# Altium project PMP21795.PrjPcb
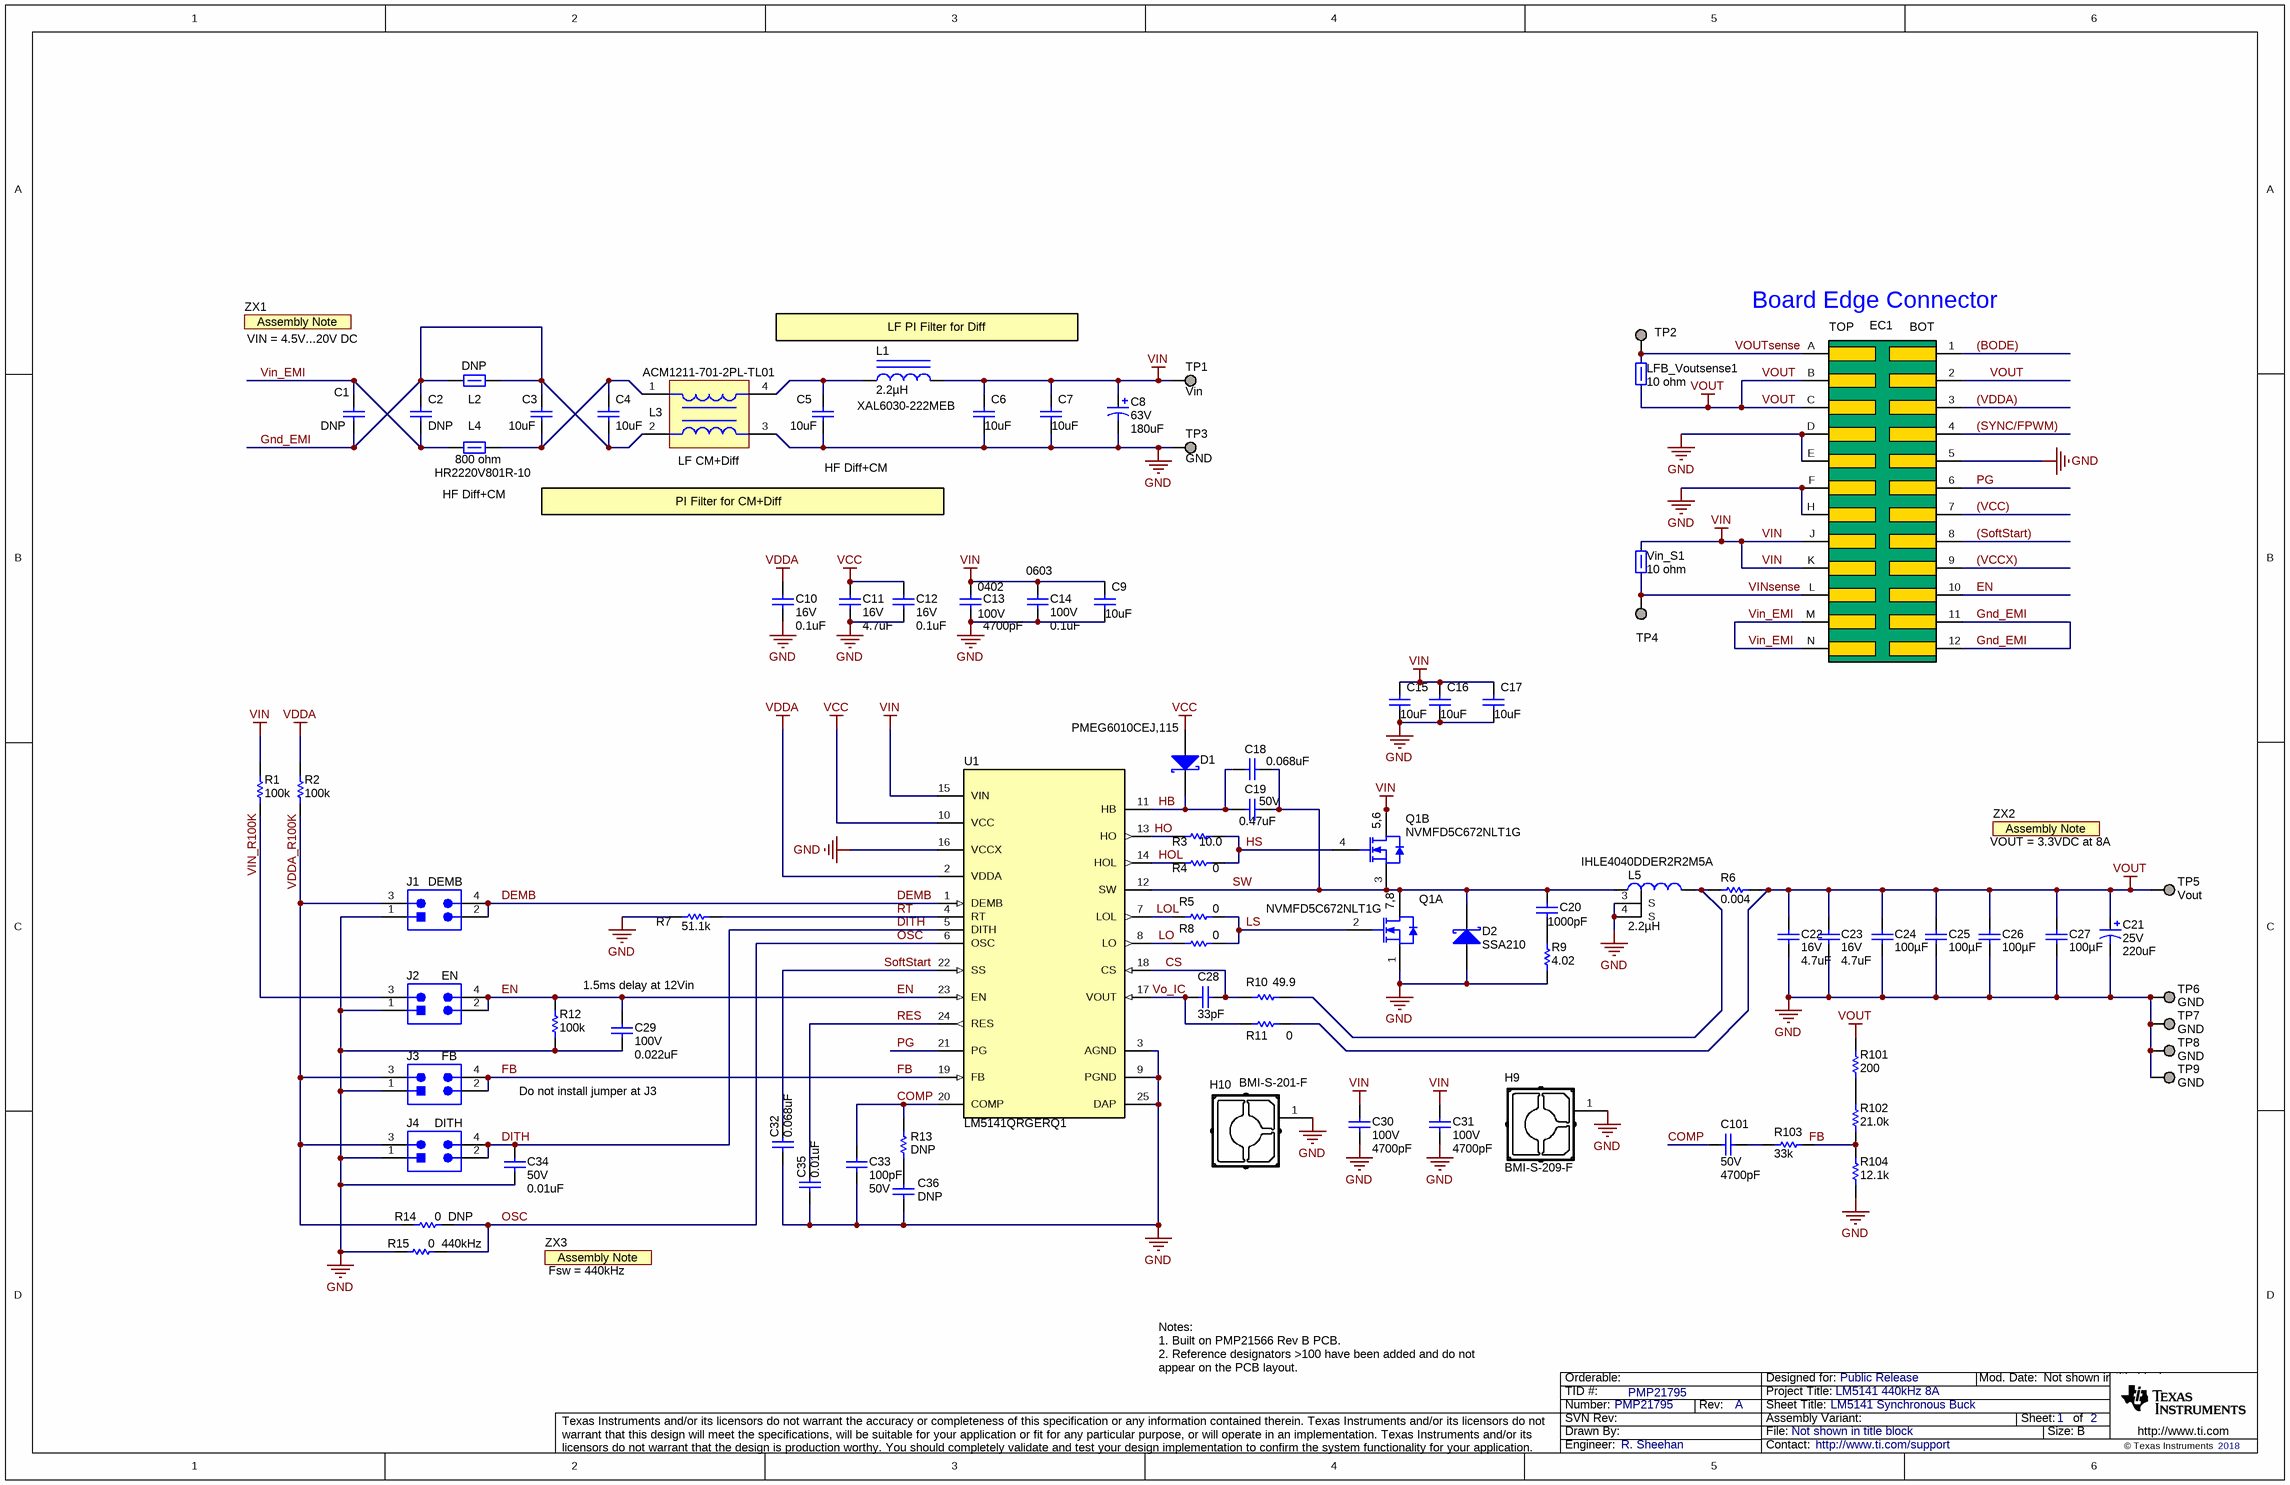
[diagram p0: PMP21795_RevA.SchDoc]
TID: PMP21795; TechSupport: http://www.ti.com/support; SCH_Rev: A; PRJ_Title: LM5141 440kHz 8A; PRJ_Number: PMP21795; PRJ_Engineer: R. Sheehan; PRJ_Customer: Public Release; PCB_Rev: B; PCB_Layout: Robert Loke; CopyrightYear: 2018
2 sheets, 104 parts. Net scope: global (net labels, ports and power ports of the same name join across sheets).
Board file: PMP21566_RevB_PCB.PcbDoc
Sheets:
  PMP21795_RevA.SchDoc
  PMP21795_RevA_HW.SchDoc

## Sheet PMP21795_RevA.SchDoc: LM5141 Synchronous Buck
size 431 x 279 mm; Date: Not shown in title block; ApprovedBy: Not shown in title block; CheckedBy: Not shown in title block; Author: Not shown in title block; CompanyName: Not shown in title block; Engineer: Not shown in title block; Organization: Not shown in title block; Address1: Not shown in title block; Address2: Not shown in title block; Address3: Not shown in title block; Address4: Not shown in title block; DocumentNumber: 1; Revision: Use project parameter SCH_Rev; SheetNumber: 1; SheetTotal: 2; PageSetup: Record=PageOptions¦CenterHorizontal=True¦CenterVertical=True¦PrintScale=0.96¦XCorrection=1.00¦YCorrection=1.00¦PrintKind=0¦BorderSize=5000000¦LeftOffset=0¦BottomOffset=0¦Orientation=2¦PaperLength=1000¦PaperWidth=1000¦Scale=100¦PaperSource=15¦PrintQuality=-3¦MediaType=1¦DitherType=10¦PrintScaleMode=1¦PaperKind=11x17¦PaperIndex=17

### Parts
C1  DNP  [1210_270L]
C2  DNP  [1210_270L]
C3  ValueDisplayed: 10uF  [1210_270L]  (hidden comment: GRM32ER71J106KA12L)
C4  ValueDisplayed: 10uF  [1210_270L]  (hidden comment: GRM32ER71J106KA12L)
C5  ValueDisplayed: 10uF  [1210_270L]  (hidden comment: GRM32ER71J106KA12L)
C6  ValueDisplayed: 10uF  [1210_270L]  (hidden comment: GRM32ER71J106KA12L)
C7  ValueDisplayed: 10uF  [1210_270L]  (hidden comment: GRM32ER71J106KA12L)
C8  VDC_V: 63V  ValueDisplayed: 180uF  [UCZ_1250x1350]  (hidden comment: UCZ1J181MNQ1MS)
C9  ValueDisplayed: 10uF  [1210_270L]  (hidden comment: GRM32ER71J106KA12L)
C10  VDC_V: 16V  ValueDisplayed: 0.1uF  [0402S]  (hidden comment: C0402C104K4RACAUTO)
C11  VDC_V: 16V  ValueDisplayed: 4.7uF  [0603S]  (hidden comment: GRM188Z71C475KE21D)
C12  VDC_V: 16V  ValueDisplayed: 0.1uF  [0402S]  (hidden comment: C0402C104K4RACAUTO)
C13  PackageReference: 0402  VDC_V: 100V  ValueDisplayed: 4700pF  [0402S]  (hidden comment: GRM155R72A472KA01D)
C14  Cap_Case: 0603  VDC_V: 100V  ValueDisplayed: 0.1uF  [0603S]  (hidden comment: GCJ188R72A104KA01D)
C15  ValueDisplayed: 10uF  [1210_270L]  (hidden comment: GRM32ER71J106KA12L)
C16  ValueDisplayed: 10uF  [1210_270L]  (hidden comment: GRM32ER71J106KA12L)
C17  ValueDisplayed: 10uF  [1210_270L]  (hidden comment: GRM32ER71J106KA12L)
C18  ValueDisplayed: 0.068uF  [0402S]  (hidden comment: C1005X7R1H683K050BB)
C19  VDC_V: 50V  ValueDisplayed: 0.47uF  [0603S]  (hidden comment: CGA3E3X7R1H474K080AB)
C20  ValueDisplayed: 1000pF  [0603S]  (hidden comment: 06031C102JAT2A)
C21  VDC_V: 25V  ValueDisplayed: 220uF  [SM_RADIAL_F]  (hidden comment: EEE-FK1E221P)
C22  VDC_V: 16V  ValueDisplayed: 4.7uF  [0603S]  (hidden comment: GRM188Z71C475KE21D)
C23  VDC_V: 16V  ValueDisplayed: 4.7uF  [0603S]  (hidden comment: GRM188Z71C475KE21D)
C24  ValueDisplayed: 100µF  [1210_280]  (hidden comment: LMK325ABJ107MMHT)
C25  ValueDisplayed: 100µF  [1210_280]  (hidden comment: LMK325ABJ107MMHT)
C26  ValueDisplayed: 100µF  [1210_280]  (hidden comment: LMK325ABJ107MMHT)
C27  ValueDisplayed: 100µF  [1210_280]  (hidden comment: LMK325ABJ107MMHT)
C28  ValueDisplayed: 33pF  [0201L]  (hidden comment: GRM0335C1H330JA01D)
C29  1.5ms delay at 12Vin  VDC_V: 100V  ValueDisplayed: 0.022uF  [0603M]
C30  VDC_V: 100V  ValueDisplayed: 4700pF  [0402S]  (hidden comment: GRM155R72A472KA01D)
C31  VDC_V: 100V  ValueDisplayed: 4700pF  [0402S]  (hidden comment: GRM155R72A472KA01D)
C32  ValueDisplayed: 0.068uF  [0402S]  (hidden comment: C1005X7R1H683K050BB)
C33  ValueDisplayed: 100pF  VDC_V: 50V  [0402]  (hidden comment: GRM1555C1H101JA01D)
C34  VDC_V: 50V  ValueDisplayed: 0.01uF  [0402S]  (hidden comment: C0402C103J5RACTU)
C35  ValueDisplayed: 0.01uF  [0402S]  (hidden comment: CGA2B3X7R1H103K050BB)
C36  DNP  [0402S]
C101  VDC_V: 50V  ValueDisplayed: 4700pF  [0402]  (hidden comment: GCM155R71H472KA37D)
D1  PMEG6010CEJ,115  [SOD-323F]
D2  SSA210  [SMA]
EC1  305-024-521-201  [Edge_Connector_EDAC_12x2]  (value not drawn)  (no BOM)
H9  BMI-S-209-F  [Laird_BMI-S-209-F]
H10  BMI-S-201-F  [Laird_BMI-S-201-F]
J1  DEMB  [TSW-102-07-G-D]
J2  EN  [TSW-102-07-G-D]
J3  FB  [TSW-102-07-G-D]
J4  DITH  [TSW-102-07-G-D]
L1  ValueDisplayed: 2.2µH  [XAL6030]  (hidden comment: XAL6030-222MEB)
L2  DNP  [2220_390]
L3  ACM1211-701-2PL-TL01  [TDK_ACM1211]
L4  800 ohm  PartNumber: HR2220V801R-10  [2220_390]
L5  ValueDisplayed: 2.2µH  [IHLE4040DD]  (hidden comment: IHLE4040DDER2R2M5A)
LFB_Voutsense1  value 10 ohm  [0402S]  (hidden comment: BLM15AX100SN1D)
Q1  NVMFD5C672NLT1G  [SO8FL_Dual]  (parts A,B of 2)
R1  ValueDisplayed: 100k  [0402S]  (hidden comment: CRCW0402100KFKED)
R2  ValueDisplayed: 100k  [0402S]  (hidden comment: CRCW0402100KFKED)
R3  ValueDisplayed: 10.0  [0402S]  (hidden comment: RMCF0402JT10R0)
R4  ValueDisplayed: 0  [0402S]  (hidden comment: RK73Z1ETTP)
R5  ValueDisplayed: 0  [0402S]  (hidden comment: RK73Z1ETTP)
R6  ValueDisplayed: 0.004  [2512_WIDE]  (hidden comment: KRL6432E-M-R004-F-T1)
R7  ValueDisplayed: 51.1k  [0402S]  (hidden comment: CRCW040251K1FKED)
R8  ValueDisplayed: 0  [0402S]  (hidden comment: RK73Z1ETTP)
R9  ValueDisplayed: 4.02  [0603]  (hidden comment: CRCW06034R02FKEA)
R10  ValueDisplayed: 49.9  [0402S]  (hidden comment: RMCF0402FT49R9)
R11  ValueDisplayed: 0  [0402S]  (hidden comment: RK73Z1ETTP)
R12  ValueDisplayed: 100k  [0402S]  (hidden comment: CRCW0402100KFKED)
R13  DNP  [0402S]
R14  DNP  ValueDisplayed: 0  [0402S]
R15  440kHz  ValueDisplayed: 0  [0402S]
R101  ValueDisplayed: 200  [0402]  (hidden comment: CRCW0402200RFKED)
R102  ValueDisplayed: 21.0k  [0402]  (hidden comment: CRCW040221K0FKED)
R103  ValueDisplayed: 33k  [0402]  (hidden comment: CRCW040233K0JNED)
R104  ValueDisplayed: 12.1k  [0402]  (hidden comment: CRCW040212K1FKED)
TP1  Vin  [Keystone1598-2]
TP2  S1751-46  [Harwin_S1751-46]  (value not drawn)
TP3  GND  [Keystone1598-2]
TP4  S1751-46  [Harwin_S1751-46]  (value not drawn)
TP5  Vout  [Keystone1598-2]
TP6  GND  [Keystone1598-2]
TP7  GND  [Keystone1598-2]
TP8  GND  [Keystone1598-2]
TP9  GND  [Keystone1598-2]
U1  LM5141QRGERQ1  [RGE0024J]
Vin_S1  value 10 ohm  [0402S]  (hidden comment: BLM15AX100SN1D)
ZX1  VIN = 4.5V...20V DC  [AssemblyNote]  (no BOM)
ZX2  VOUT = 3.3VDC at 8A  [AssemblyNote]  (no BOM)
ZX3  Fsw = 440kHz  [AssemblyNote]  (no BOM)

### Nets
GND: C5.2 C6.2 C7.2 C8.2(-) C9.2 C10.1 C11.2 C12.1 C13.2 C14.2 C15.2 C16.2 C17.2 C21.2(-) C22.2 C23.2 C24.2 C25.2 C26.2 C27.2 C29.2 C30.2 C31.2 C32.2 C33.2 C34.1 C35.2 C36.2 D2.2(A) EC1.5 EC1.D EC1.E EC1.F EC1.H H9.1 H10.1 J1.1 J2.1 J3.1 J4.1 L3.3 L5.3(S) L5.4(S) Q1.1(S) R7.2 R9.1 R12.1 R15.2 R104.1 TP3.1 TP6.1 TP7.1 TP8.1 TP9.1 U1.3(AGND) U1.9(PGND) U1.16(VCCX) U1.25(DAP)
VCC: C11.1 C12.2 D1.2(A) U1.10(VCC)
VDDA: C10.2 R2.2 U1.2(VDDA)
VIN: C6.1 C7.1 C8.1(+) C9.1 C13.1 C14.1 C15.1 C16.1 C17.1 C30.1 C31.1 EC1.J EC1.K L1.2 Q1.5(D) Q1.6(D) R1.2 TP1.1 U1.15(VIN) Vin_S1.2
VOUT: C21.1(+) C22.1 C23.1 C24.1 C25.1 C26.1 C27.1 EC1.2 EC1.B EC1.C LFB_Voutsense1.1 R6.2 R11.1 R101.2 TP5.1
(BODE): EC1.1
(SoftStart): EC1.8
(SYNC/FPWM): EC1.4
(VCC): EC1.7
(VCCX): EC1.9
(VDDA): EC1.3
COMP: C33.1 C101.1 R13.2 U1.20(COMP)
CS: C28.1 R10.2 U1.18(CS)
DEMB: J1.2 J1.4 U1.1(DEMB)
DITH: C34.2 J4.2 J4.4 U1.5(DITH)
EN: C29.1 EC1.10 J2.2 J2.4 R12.2 U1.23(EN)
FB: J3.2 J3.4 U1.19(FB)
Gnd_EMI: C1.2 C2.1 C3.1 C4.2 EC1.11 EC1.12 L2.1 L2.2 L3.2
HB: C18.1 C19.2 D1.1(K) U1.11(HB)
HO: R3.1 U1.13(HO)
HOL: R4.1 U1.14(HOL)
HS: Q1.4(G) R3.2 R4.2
LO: R8.1 U1.8(LO)
LOL: R5.1 U1.7(LOL)
LS: Q1.2(G) R5.2 R8.2
OSC: R14.1 R15.1 U1.6(OSC)
PG: EC1.6 U1.21(PG)
RES: C35.1 U1.24(RES)
RT: R7.1 U1.4(RT)
SoftStart: C32.1 U1.22(SS)
SW: C18.2 C19.1 C20.1 D2.1(K) L5.1 Q1.3(S) Q1.7(D) Q1.8(D) U1.12(SW)
VDDA_R100K: J1.3 J3.3 J4.3 R2.1 R14.2
Vin_EMI: C1.1 C2.2 EC1.M EC1.N L4.1
VIN_R100K: J2.3 R1.1
VINsense: EC1.L TP4.1 Vin_S1.1
Vo_IC: C28.2 R11.2 U1.17(VOUT)
VOUTsense: EC1.A LFB_Voutsense1.2 TP2.1
NetC3_2: C3.2 C4.1 L3.1 L4.2
NetC5_1: C5.1 L1.1 L3.4
NetC20_2: C20.2 R9.2
NetC36_1: C36.1 R13.1
NetC101_2: C101.2 R103.2
NetL5_2: L5.2 R6.1 R10.1
NetR101_1: R101.1 R102.2
NetR102_1: R102.1 R103.1 R104.2

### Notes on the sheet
- (near EC1) Board Edge Connector
- LF PI Filter for Diff
- (near L4) HF Diff+CM
- (near L3) LF CM+Diff
- PI Filter for CM+Diff
- (near C5) HF Diff+CM
- Do not install jumper at J3
- Notes:
  1. Built on PMP21566 Rev B PCB.
  2. Reference designators >100 have been added and do not appear on the PCB layout.
- Labels drawn without touching a wire or pin: FB

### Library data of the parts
C1 C2 = CMP-0009229-2: CAP, CERM, 10 uF, 63 V, +/- 10%, X7R, 1210; Manufacturer: MuRata; PartNumber: GRM32ER71J106KA12L; TaMin_C: -55°C; Polarized: N; SizeAreaWB_mm2: 14.7; Value1: Unknown; U/M: EA; Value: 10uF; TaMax_C: 125°C; SizeZ_mm: 2.7; SizeX_mm: 3.2; SizeY_mm: 2.5; Cap_Case: 1210; Value2: 63V; SizeArea_mm2: 8; CompType: Capacitor; Cap_F: 10µF; AEC Category: Q200
C3-C7 C9 C15-C17 = CMP-0009229-2: CAP, CERM, 10 uF, 63 V, +/- 10%, X7R, 1210; Manufacturer: MuRata; TaMin_C: -55°C; Polarized: N; SizeAreaWB_mm2: 14.7; Value1: Unknown; U/M: EA; Value: 10uF; TaMax_C: 125°C; SizeZ_mm: 2.7; SizeX_mm: 3.2; SizeY_mm: 2.5; Cap_Case: 1210; Value2: 63V; SizeArea_mm2: 8; CompType: Capacitor; Cap_F: 10µF; AEC Category: Q200
C8 = CMP-0011410-2: CAP, AL, 180 uF, 63 V, +/- 20%, 0.2 ohm, AEC-Q200 Grade 1, SMD; Manufacturer: Nichicon; TaMin_C: -40°C; Polarized: Y; SizeAreaWB_mm2: 258.96; Value1: 0.2 ohm; U/M: EA; Value: 180uF; TaMax_C: 125°C; SizeZ_mm: 14.5; SizeX_mm: 14.6; SizeY_mm: 13.6; Cap_Case: 12.5x13.5mm; SizeArea_mm2: 198.56; CompType: Capacitor; Cap_F: 180µF; IRMS_A: 1A; AEC Category: Q200; AEC Grade: 1; ESR_ohm: 2d
C10 C12 = CMP-0006237-2: CAP, CERM, 0.1 uF, 16 V, +/- 10%, X7R, AEC-Q200 Grade 1, 0402; Manufacturer: Kemet; TaMin_C: -55°C; Polarized: N; SizeAreaWB_mm2: 3; Value1: Unknown; U/M: EA; Value: 0.1uF; TaMax_C: 125°C; SizeZ_mm: 0.6; SizeX_mm: 1; SizeY_mm: 0.5; Cap_Case: 0402; CompType: Capacitor; AEC Qualified: Y; Cap_F: 100nF; AEC Category: Q200
C11 C22 C23 = CMP-0064936-4: CAP, CERM, 4.7 uF, 16 V,+/- 10%, X7R, 0603; Manufacturer: MuRata; TaMin_C: -55°C; Polarized: N; SizeAreaWB_mm2: 4.68; Value1: Unknown; U/M: EA; Value: 4.7uF; TaMax_C: 125°C; SizeZ_mm: 1; SizeX_mm: 1.6; SizeY_mm: 0.8; Cap_Case: 0603; SizeArea_mm2: 1.28; CompType: Capacitor; Cap_F: 4.7µF; AEC Category: Q200
C13 = CMP-0006712-2: CAP, CERM, 4700 pF, 100 V, +/- 10%, X7R, 0402; Manufacturer: MuRata; TaMin_C: -55°C; Polarized: N; SizeAreaWB_mm2: 3; Value1: Unknown; U/M: EA; Value: 4700pF; TaMax_C: 125°C; SizeZ_mm: 0.6; SizeX_mm: 1; SizeY_mm: 0.5; CompType: Capacitor; Cap_F: 4.7nF; AEC Category: Q200
C14 = CMP-0064935-4: CAP, CERM, 0.1 uF, 100 V,+/- 10%, X7R, AEC-Q200 Grade 1, 0603; Manufacturer: MuRata; TaMin_C: -55°C; Polarized: N; SizeAreaWB_mm2: 4.68; Value1: Unknown; U/M: EA; Value: 0.1uF; TaMax_C: 125°C; SizeZ_mm: 1; SizeX_mm: 1.6; SizeY_mm: 0.8; SizeArea_mm2: 1.28; CompType: Capacitor; AEC Qualified: Y; Cap_F: 100nF; AEC Category: Q200
C18 C32 = CMP-0006299-2: CAP, CERM, 0.068 uF, 50 V, +/- 10%, X7R, 0402; Manufacturer: TDK; TaMin_C: -55°C; ESR_ohm: 0.05606; Polarized: N; SizeAreaWB_mm2: 3; Value1: 0.05606 ohm; U/M: EA; TaMax_C: 125°C; SizeZ_mm: 0.6; SizeX_mm: 1; SizeY_mm: 0.5; Cap_Case: 0402; Value2: 50V; CompType: Capacitor; Cap_F: 68nF; IRMS_A: 6.84724dA; AEC Category: Q200
C19 = CMP-0007096-4: CAP, CERM, 0.47 uF, 50 V, +/- 10%, X7R, AEC-Q200 Grade 1, 0603; Manufacturer: TDK; TaMin_C: -55°C; ESR_ohm: 0.01064; Polarized: N; SizeAreaWB_mm2: 4.68; Value1: 0.01064 ohm; U/M: EA; Value: 0.47uF; TaMax_C: 125°C; SizeZ_mm: 1; SizeX_mm: 1.6; SizeY_mm: 0.8; Cap_Case: 0603; SizeArea_mm2: 1.28; CompType: Capacitor; AEC Qualified: Y; Cap_F: 470nF; IRMS_A: 1.59966A; AEC Category: Q200
C20 = CMP-0006723-4: CAP, CERM, 1000 pF, 100 V, +/- 5%, X7R, 0603; Manufacturer: AVX; TaMin_C: -55°C; ESR_ohm: 2.76d; Polarized: N; SizeAreaWB_mm2: 4.68; Value1: 0.276 ohm; U/M: EA; Value: 1000pF; TaMax_C: 125°C; SizeZ_mm: 1; SizeX_mm: 1.6; SizeY_mm: 0.8; Cap_Case: 0603; Value2: 100V; SizeArea_mm2: 1.28; CompType: Capacitor; Cap_F: 1nF; AEC Category: Q200
C21 = CMP-0010714-1: CAP, AL, 220 uF, 25 V, +/- 20%, 0.16 ohm, AEC-Q200 Grade 2, SMD; Manufacturer: Panasonic; TaMin_C: -55°C; ESR_ohm: 1.6d; Polarized: Y; SizeAreaWB_mm2: 123.6; U/M: EA; Value: 220uF; TaMax_C: 105°C; SizeZ_mm: 10.2; SizeX_mm: 10; SizeY_mm: 8.3; Cap_Case: F; SizeArea_mm2: 83; CompType: Capacitor; Cap_F: 220µF; IRMS_A: 6dA; AEC Grade: 2; AEC Category: Q200
C24 C25 = LMK325ABJ107MMHT: CAP, CERM, 100 µF, 10 V, +/- 20%, X5R, AEC-Q200 Grade 3, 1210; Manufacturer: Taiyo Yuden; Polarized: N; CompType: Capacitor; Value: 100uF; U/M: EA; Cap_F: 0.0001; Tolerance_%: 20; Value1: Unknown; VDC_V: 10; Value2: 10V; TaMin_C: -55; TaMax_C: 85; Cap_Case: 1210; SizeArea_mm2: 8; SizeAreaWB_mm2: 14.7; SizeX_mm: 3.2; SizeY_mm: 2.5; SizeZ_mm: 2.8; AEC Category: Q200; AEC Qualified: Y; AEC Grade: 3
C26 C27 = LMK325ABJ107MMHT: CAP, CERM, 100 µF, 10 V,+/- 20%, X5R, AEC-Q200 Grade 3, 1210; Manufacturer: Taiyo Yuden; Polarized: N; CompType: Capacitor; Value: 100uF; U/M: EA; Cap_F: 0.0001; Tolerance_%: 20; VDC_V: 10; Value2: 10V; TaMin_C: -55; TaMax_C: 85; Cap_Case: 1210; AEC Category: Q200; AEC Qualified: Y; AEC Grade: 3; SizeArea_mm2: 8; SizeAreaWB_mm2: 14.7; SizeX_mm: 3.2; SizeY_mm: 2.5; SizeZ_mm: 2.8
C28 = GRM0335C1H330JA01D: CAP, CERM, 33 pF, 50 V,+/- 5%, C0G/NP0, 0201; Manufacturer: MuRata; Polarized: N; CompType: Capacitor; Value: 33pF; U/M: EA; Cap_F: 0.000000000033; Tolerance_%: 5; VDC_V: 50; Value2: 50V; TaMin_C: -55; TaMax_C: 125; Cap_Case: 0201; SizeArea_mm2: 0.18; SizeAreaWB_mm2: 2.08; SizeX_mm: 0.6; SizeY_mm: 0.3; SizeZ_mm: 0.26; AEC Category: Q200
C29 = CMP-0007086-4: CAP, CERM, 0.022 uF, 100 V, +/- 10%, X7R, AEC-Q200 Grade 1, 0603; Manufacturer: TDK; PartNumber: CGA3E2X7R2A223K080AA; TaMin_C: -55°C; ESR_ohm: 0.083542; Polarized: N; SizeAreaWB_mm2: 4.68; Value1: 0.083542 ohm; U/M: EA; TaMax_C: 125°C; SizeZ_mm: 1; SizeX_mm: 1.6; SizeY_mm: 0.8; Cap_Case: 0603; SizeArea_mm2: 1.28; CompType: Capacitor; AEC Qualified: Y; Cap_F: 22nF; IRMS_A: 6.09312dA; AEC Category: Q200
C30 C31 = CMP-0006712-2: CAP, CERM, 4700 pF, 100 V, +/- 10%, X7R, 0402; Manufacturer: MuRata; TaMin_C: -55°C; Polarized: N; SizeAreaWB_mm2: 3; Value1: Unknown; U/M: EA; Value: 4700pF; TaMax_C: 125°C; SizeZ_mm: 0.6; SizeX_mm: 1; SizeY_mm: 0.5; Cap_Case: 0402; CompType: Capacitor; Cap_F: 4.7nF; AEC Category: Q200
C33 = CMP-0006410-2: CAP, CERM, 100 pF, 50 V, +/- 5%, C0G/NP0, 0402; Manufacturer: MuRata; Polarized: N; Value: 100pF; U/M: EA; Value1: Unknown; TaMin_C: -55°C; TaMax_C: 125°C; SizeArea_mm2: 0.5; SizeAreaWB_mm2: 3; SizeX_mm: 1; SizeZ_mm: 0.6; AEC Category: Q200
C34 = CMP-0006236-2: CAP, CERM, 0.01 uF, 50 V, +/- 5%, X7R, 0402; Manufacturer: Kemet; TaMin_C: -55°C; Polarized: N; SizeAreaWB_mm2: 3; Value1: Unknown; U/M: EA; Value: 0.01uF; TaMax_C: 125°C; SizeZ_mm: 0.6; SizeX_mm: 1; SizeY_mm: 0.5; Cap_Case: 0402; CompType: Capacitor; Cap_F: 10nF; AEC Category: Q200
C35 = CMP-0006324-2: CAP, CERM, 0.01 uF, 50 V, +/- 10%, X7R, AEC-Q200 Grade 1, 0402; Manufacturer: TDK; TaMin_C: -55°C; ESR_ohm: 3.33065d; Polarized: N; SizeAreaWB_mm2: 3; Value1: 0.333065 ohm; U/M: EA; Value: 0.01uF; TaMax_C: 125°C; SizeZ_mm: 0.6; SizeX_mm: 1; SizeY_mm: 0.5; Cap_Case: 0402; Value2: 50V; CompType: Capacitor; AEC Qualified: Y; Cap_F: 10nF; IRMS_A: 3.23373dA; AEC Category: Q200
C36 = CMP-0006324-2: CAP, CERM, 0.01 uF, 50 V, +/- 10%, X7R, AEC-Q200 Grade 1, 0402; Manufacturer: TDK; PartNumber: CGA2B3X7R1H103K050BB; TaMin_C: -55°C; ESR_ohm: 3.33065d; Polarized: N; SizeAreaWB_mm2: 3; Value1: 0.333065 ohm; U/M: EA; Value: 0.01uF; TaMax_C: 125°C; SizeZ_mm: 0.6; SizeX_mm: 1; SizeY_mm: 0.5; Cap_Case: 0402; Value2: 50V; CompType: Capacitor; AEC Qualified: Y; Cap_F: 10nF; IRMS_A: 3.23373dA; AEC Category: Q200
C101 = CMP-0006361-2: CAP, CERM, 4700 pF, 50 V, +/- 10%, X7R, AEC-Q200 Grade 1, 0402; Manufacturer: MuRata; TaMin_C: -55°C; Polarized: N; SizeAreaWB_mm2: 3; Value1: Unknown; U/M: EA; Value: 4700pF; TaMax_C: 125°C; SizeZ_mm: 0.6; SizeX_mm: 1; SizeY_mm: 0.5; AEC Qualified: Y; Cap_F: 4.7nF; AEC Category: Q200
D1 = PMEG6010CEJ,115: Diode, Schottky, 60 V, 1 A, SOD-323F; Manufacturer: NXP Semiconductor; U/M: EA; Vf_V: 0.66; Value: 60V; Value1: 1A; Value2: 0.66V; Io_A: 1; Vr_V: 60; TJmax_C: 150
D2 = CMP-0028811-1: Diode, Schottky, 100 V, 2 A, AEC-Q101, SMA; Manufacturer: Fairchild Semiconductor; Io_A: 2A; Green_Lifecycle: Not Set; SizeAreaWB_mm2: 37.3428; Vr_V: 100V; Green_REACh: Incomplete; TJmax_C: 175°C; U/M: EA; Value: 100V; SizeZ_mm: 2.87; SizeX_mm: 5.59; SizeY_mm: 2.92; Vf_V: 8dV; Value2: 0.8V; SizeArea_mm2: 16.3228; AEC Qualified: Y; AEC Category: Q101
EC1 = 305-024-521-201: Edge Connector; Manufacturer: Edac Inc.; SymbolCreator: a0799628; CompType: Card Edge Footprint; Note: PartNumber and Manufacturer are for matching connector
H9 = CMP-0003727-1: Standard Surface Mount Shield , Height 7mm; Manufacturer: Laird-Signal Integrity Products; CompType: Hardware
H10 = CMP-0003716-1: EMI SHIELD, 13.66 x 12.70 mm, SMT; Manufacturer: Laird-Signal Integrity Products
J1-J4 = CMP-0075404-1: Header, 100mil, 2x2, Gold, TH; Manufacturer: Samtec; Pitch_mm: 2.54; Cert_VDE: N; Gender: Male; Cert_CSA: Y; Voltage_V: 550V; Green_REACh: Passed; Current_A: 6.3A; CT: False; Green_Lifecycle: Active; Row_Count: 2; CNHeader: True
L1 = CMP-0061015-2: Inductor, Shielded, Composite, 2.2 µH, 10 A, 0.01397 ohm, AEC-Q200 Grade 1, SMD; Manufacturer: Coilcraft; Isat: 15.9A @ 30% inductance drop; Irms: 10A @ 40C rise; Green_Lifecycle: Not Set; SizeAreaWB_mm2: 71.5616; Green_REACh: Incomplete; Value: 2.2uH; Imax_A: 10A; SizeZ_mm: 3.1; SizeX_mm: 6.36; SizeY_mm: 6.56; SizeArea_mm2: 41.7216; AEC Qualified: Y; AEC Category: Q200; AEC Grade: 1
L2 = CMP-0003396-1: Ferrite Bead, 800 ohm @ 100 MHz, 8 A, 2220; Manufacturer: Laird-Signal Integrity Products; PartNumber: HR2220V801R-10; Ztyp@1GHz_Ohm: 75; ZTyp@100MHz_Ohm: 800; SizeAreaWB_mm2: 53.96; DCR_ohm: 0.01; Value1: 0.01 ohm; Value: 800 ohm; Imax_A: 8A; SizeZ_mm: 3.9; SizeX_mm: 5.6; SizeY_mm: 5.1; SizeArea_mm2: 28.56
L3 = CMP-0013118-2: Coupled inductor, 8 A, 0.006 ohm, SMD; Manufacturer: TDK; DCR_ohm: 6m
L4 = CMP-0003396-1: Ferrite Bead, 800 ohm @ 100 MHz, 8 A, 2220; Manufacturer: Laird-Signal Integrity Products; Ztyp@1GHz_Ohm: 75; ZTyp@100MHz_Ohm: 800; SizeAreaWB_mm2: 53.96; DCR_ohm: 0.01; Value1: 0.01 ohm; Imax_A: 8A; SizeZ_mm: 3.9; SizeX_mm: 5.6; SizeY_mm: 5.1; SizeArea_mm2: 28.56
L5 = CMP-0082363-1: Inductor, Shielded, 2.2 µH, 12 A, 0.00876 ohm, AEC-Q200 Grade 0, SMD; Manufacturer: Vishay-Dale; Isat: 12A @ 20% inductance drop; Irms: 15A @ 40C rise; SizeAreaWB_mm2: 165.6344; DCR_ohm: 8.76m; Value: 2.2uH; Imax_A: 12A; SizeZ_mm: 4.42; SizeX_mm: 10.92; SizeY_mm: 10.82; SizeArea_mm2: 118.1544; AEC Qualified: Y; AEC Grade: 0; AEC Category: Q200
LFB_Voutsense1 Vin_S1 = BLM15AX100SN1D: Ferrite Bead, 10 ohm @ 100 MHz, 1.74 A, 0402; Manufacturer: MuRata; Imax_A: 1.74; DCR_ohm: 0.015; Value1: 0.015 ohm; Value2: 1.74A; ZTyp@100MHz_Ohm: 10
Q1 = CMP-0082232-1: MOSFET, 2-CH, N-CH, 60 V, 49 A, AEC-Q101, 4.9x5.9mm; Manufacturer: ON Semiconductor; Alternate Manufacturer: None; ChType: N; QgTyp_nC: 5.7; SizeAreaWB_mm2: 58.2725; SizeArea_mm2: 31.6725; IdsMax_A: 49A; AEC Qualified: Y; VdsMax_V: 60V; Rdson45_ohm: 0.0168; Vgs_V: 20V; AEC Category: Q101; Value: 60V; SizeZ_mm: 1.1; ChMode: Enhancement; SizeY_mm: 5.15; Value2: 5.7 nC; Value1: 0.0168 ohm; SizeX_mm: 6.15
R1 R2 = CMP-0025950-2: RES, 100 k, 1%, 0.063 W, 0402; Manufacturer: Vishay-Dale; Power_W: 63mW; TempCo: 100 ppm/C; U/M: EA; Value: 100k; EIA_Code: E96; SizeX_mm: 1; SizeY_mm: 0.5; SizeZ_mm: 0.6; Value2: 0.063W; CompType: Resistor; VDC_V: 50V; AEC Category: Q200
R3 = CMP-0026764-1: RES, 10.0, 1%, 0.063 W, AEC-Q200 Grade 0, 0402; Manufacturer: Stackpole Electronics Inc; Power_W: 63mW; TempCo: 100 ppm/C; Value_Code: 10R0; U/M: EA; Value: 10.0; EIA_Code: E96; Res_ohm: 10; SizeX_mm: 1; SizeY_mm: 0.5; SizeZ_mm: 0.6; Value2: 0.063W; CompType: Resistor; AEC Qualified: Y; AEC Grade: 0; AEC Category: Q200
R4 R5 R8 R11 = CMP-0027007-2: RES, 0, 5%, 0.063 W, AEC-Q200 Grade 0, 0402; Manufacturer: KOA Speer; Power_W: 63mW; TempCo: ppm/C; Value_Code: 0000; U/M: EA; Value: 0; EIA_Code: E24; SizeX_mm: 1; SizeY_mm: 0.5; SizeZ_mm: 0.6; Value2: 0.063W; CompType: Resistor; AEC Qualified: Y; AEC Category: Q200
R6 = CMP-0015107-2: RES, 0.004, 1%, 3 W, 2512 WIDE; Manufacturer: Susumu Co Ltd; Value: 0.004; Res_ohm: 4m; Value_Code: 4L000; Power_W: 3W; TempCo: 50 ppm/C; SizeArea_mm2: 20.16; SizeX_mm: 3.2; SizeY_mm: 6.3; SizeZ_mm: 0.7; AEC Category: Q200; SizeAreaWB_mm2: 43.16; U/M: EA
R7 = CMP-0026437-1: RES, 51.1 k, 1%, 0.063 W, 0402; Manufacturer: Vishay-Dale; Power_W: 63mW; TempCo: 100 ppm/C; Value_Code: 51k1; U/M: EA; Value: 51.1k; EIA_Code: E96; SizeX_mm: 1; SizeY_mm: 0.5; SizeZ_mm: 0.6; Value2: 0.063W; CompType: Resistor; VDC_V: 50V; AEC Category: Q200
R9 = CMP-0022469-4: RES, 4.02, 1%, 0.1 W, AEC-Q200 Grade 0, 0603; Manufacturer: Vishay-Dale; Power_W: 100mW; TempCo: 100 ppm/C; Value_Code: 4R02; Value: 4.02; EIA_Code: E96; SizeX_mm: 1.6; SizeY_mm: 0.8; SizeZ_mm: 1; Value2: 0.1W; SizeArea_mm2: 1.28; AEC Qualified: Y; VDC_V: 75V; AEC Category: Q200; AEC Grade: 0
R10 = CMP-0026761-1: RES, 49.9, 1%, 0.063 W, AEC-Q200 Grade 0, 0402; Manufacturer: Stackpole Electronics Inc; Power_W: 63mW; TempCo: 100 ppm/C; Value_Code: 49R9; U/M: EA; Value: 49.9; EIA_Code: E96; SizeX_mm: 1; SizeY_mm: 0.5; SizeZ_mm: 0.6; Value2: 0.063W; CompType: Resistor; AEC Qualified: Y; VDC_V: 50V; AEC Grade: 0; AEC Category: Q200
R12 = CMP-0025950-3: RES, 100 k, 1%, 0.063 W, AEC-Q200 Grade 0, 0402; Manufacturer: Vishay-Dale; Power_W: 63mW; TempCo: 100 ppm/C; Value: 100k; EIA_Code: E96; SizeX_mm: 1; SizeY_mm: 0.5; SizeZ_mm: 0.6; Value2: 0.063W; CompType: Resistor; AEC Qualified: Y; VDC_V: 50V; AEC Grade: 0; AEC Category: Q200
R13 = CMP-0026162-2: RES, 20.0 k, 1%, 0.063 W, AEC-Q200 Grade 0, 0402; Manufacturer: Vishay-Dale; PartNumber: CRCW040220K0FKED; Power_W: 63mW; TempCo: 100 ppm/C; Value_Code: 20k0; Value: 20.0k; EIA_Code: E96; Res_ohm: 20k; SizeX_mm: 1; SizeY_mm: 0.5; SizeZ_mm: 0.6; Value2: 0.063W; CompType: Resistor; AEC Qualified: Y; VDC_V: 50V; AEC Category: Q200; AEC Grade: 0
R14 R15 = CMP-0027002-2: RES, 0, 5%, 0.063 W, 0402; Manufacturer: Rohm; PartNumber: MCR01MZPJ000; Power_W: 63mW; TempCo: 500 ppm/C; Value_Code: 0000; U/M: EA; Value: 0; EIA_Code: E24; SizeX_mm: 1; SizeY_mm: 0.5; SizeZ_mm: 0.6; Value2: 0.063W; CompType: Resistor; VDC_V: 50V; AEC Category: Q200
R101 = CMP-0026159-2: RES, 200, 1%, 0.063 W, AEC-Q200 Grade 0, 0402; Manufacturer: Vishay-Dale; Power_W: 63mW; TempCo: 100 ppm/C; Value_Code: 200R; Value: 200; EIA_Code: E96; SizeX_mm: 1; SizeY_mm: 0.5; SizeZ_mm: 0.6; Value2: 0.063W; AEC Qualified: Y; VDC_V: 50V; AEC Category: Q200; AEC Grade: 0
R102 = CMP-0026170-2: RES, 21.0 k, 1%, 0.063 W, AEC-Q200 Grade 0, 0402; Manufacturer: Vishay-Dale; Power_W: 63mW; TempCo: 100 ppm/C; Value_Code: 21k0; Value: 21.0k; EIA_Code: E96; Res_ohm: 21k; SizeX_mm: 1; SizeY_mm: 0.5; SizeZ_mm: 0.6; Value2: 0.063W; AEC Qualified: Y; VDC_V: 50V; AEC Category: Q200; AEC Grade: 0
R103 = CMP-0026907-3: RES, 33 k, 5%, 0.063 W, AEC-Q200 Grade 0, 0402; Manufacturer: Vishay-Dale; Power_W: 63mW; TempCo: 200 ppm/C; Value_Code: 33k0; Value: 33k; EIA_Code: E24; SizeX_mm: 1; SizeY_mm: 0.5; SizeZ_mm: 0.6; Value2: 0.063W; AEC Qualified: Y; VDC_V: 50V; AEC Category: Q200; AEC Grade: 0
R104 = CMP-0025991-3: RES, 12.1 k, 1%, 0.063 W, AEC-Q200 Grade 0, 0402; Manufacturer: Vishay-Dale; Power_W: 63mW; TempCo: 100 ppm/C; Value_Code: 12k1; Value: 12.1k; EIA_Code: E96; SizeX_mm: 1; SizeY_mm: 0.5; SizeZ_mm: 0.6; Value2: 0.063W; AEC Qualified: Y; VDC_V: 50V; AEC Category: Q200; AEC Grade: 0
TP1 TP3 TP5-TP9 = 1598-2: Terminal, Turret, TH, Triple; Manufacturer: Keystone; CompType: Turret Terminal; U/M: EA
TP2 TP4 = CMP-0075188-1: Test Lead clips and hooks, SMT; Manufacturer: Harwin; CNHeader: False; Current_A: 2A; CompType: Test Point; ContactFinish: Tin; CT: True
U1 = CMP-0076290-1: Wide Input 2.2MHz low Iq Synchronous Buck Controller, RGE0024J (VQFN-24); Alternate Manufacturer: Texas Instruments; SizeX_mm: 4.0; CompType: IC; SizeAreaWB_mm2: 25.0; SizeZ_mm: 1.0; U/M: EA; SizeArea_mm2: 16.0
ZX1-ZX3 = AssemblyNote: This Assembly Note will show in the PcbDoc and associated outputs; SymbolCreator: codlsc

## Sheet PMP21795_RevA_HW.SchDoc: LM5141 Hardware
size 431 x 279 mm; Date: Not shown in title block; ApprovedBy: Not shown in title block; CheckedBy: Not shown in title block; Author: Not shown in title block; CompanyName: Not shown in title block; Engineer: Not shown in title block; Organization: Not shown in title block; Address1: Not shown in title block; Address2: Not shown in title block; Address3: Not shown in title block; Address4: Not shown in title block; DocumentNumber: 2; Revision: Use project parameter SCH_Rev; SheetNumber: 2; SheetTotal: 2; PageSetup: Record=PageOptions¦CenterHorizontal=True¦CenterVertical=True¦PrintScale=1.00¦XCorrection=1.00¦YCorrection=1.00¦PrintKind=0¦BorderSize=5000000¦LeftOffset=0¦BottomOffset=0¦Orientation=2¦PaperLength=1000¦PaperWidth=1000¦Scale=100¦PaperSource=15¦PrintQuality=600¦MediaType=1¦DitherType=10¦PaperKind=Letter¦PrintScaleMode=1
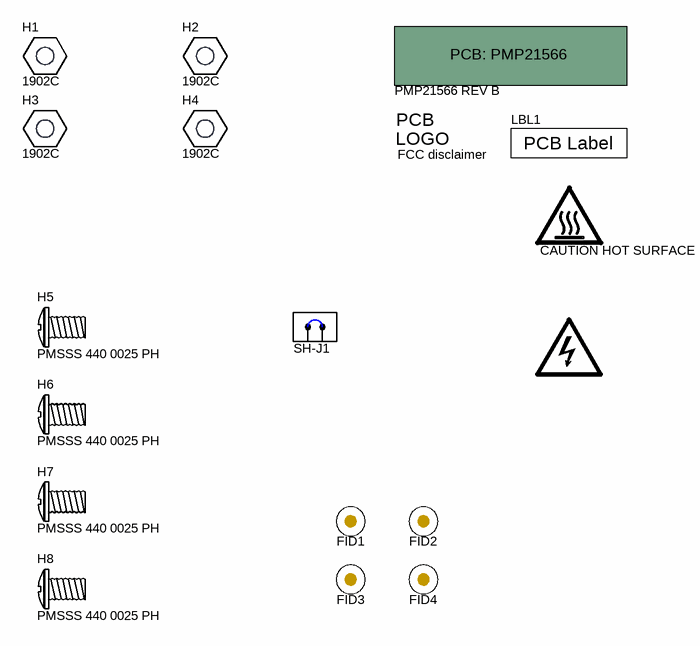
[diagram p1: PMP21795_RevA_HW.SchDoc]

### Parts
!PCB1  PMP21566 REV B  (mechanical)
FID1  Fiducial  [Fiducial10-20]  (value not drawn)
FID2  Fiducial  [Fiducial10-20]  (value not drawn)
FID3  Fiducial  [Fiducial10-20]  (value not drawn)
FID4  Fiducial  [Fiducial10-20]  (value not drawn)
H1  1902C  [Keystone_1902C]
H2  1902C  [Keystone_1902C]
H3  1902C  [Keystone_1902C]
H4  1902C  [Keystone_1902C]
H5  PMSSS 440 0025 PH  [B_F_PMSSS4400025PH]
H6  PMSSS 440 0025 PH  [B_F_PMSSS4400025PH]
H7  PMSSS 440 0025 PH  [B_F_PMSSS4400025PH]
H8  PMSSS 440 0025 PH  [B_F_PMSSS4400025PH]
LBL1  (no value)  [Label_650x200]
Logo1  FCC disclaimer  [FCC_disclaimer]  (no BOM)
Logo3  CAUTION HOT SURFACE  [IEC_HotSurface_Small]  (no BOM)
Logo5  DANGER HIGH VOLTAGE  [IEC_HighVoltage_Small]  (value not drawn)  (no BOM)
SH-J1  60900213421  [Wurth_60900213421]  (value not drawn)  (mechanical)

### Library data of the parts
!PCB1 = PCB_OtherProject: Manufacturer: Any; SymbolCreator: a0412235; CompType: PCB; U/M: EA
FID1-FID4 = Fiducial: Fiducial mark.  There is nothing to buy or mount.; SymbolCreator: codlsc
H1-H4 = 1902C: Standoff, Hex, 0.5"L #4-40 Nylon; Manufacturer: Keystone; CompType: Hardware
H5-H8 = CMP-0003715-1: MACHINE SCREW PAN PHILLIPS 4-40; Manufacturer: B&F Fastener Supply; CompType: Standoff
LBL1 = THT-14-423-10: Thermal Transfer Printable Labels, 0.650" W x 0.200" H - 10,000 per roll; Manufacturer: Brady; SymbolCreator: a0412235; CompType: Label
Logo1 = FCC_disclaimer: SymbolCreator: codlsc
Logo3 = IEC_HotSurface: IEC 61010-1 Hot Surface Warning; SymbolCreator: a0412235
Logo5 = IEC_HighVoltage: IEC 61010-1 High Voltage Warning; SymbolCreator: a0412235
SH-J1 = 60900213421: Shunt, 2.54mm, Gold, Black; Manufacturer: Wurth Elektronik

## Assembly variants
001: not fitted C1 C2 C36 FID1 FID2 FID3 FID4 L2 R13 R14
